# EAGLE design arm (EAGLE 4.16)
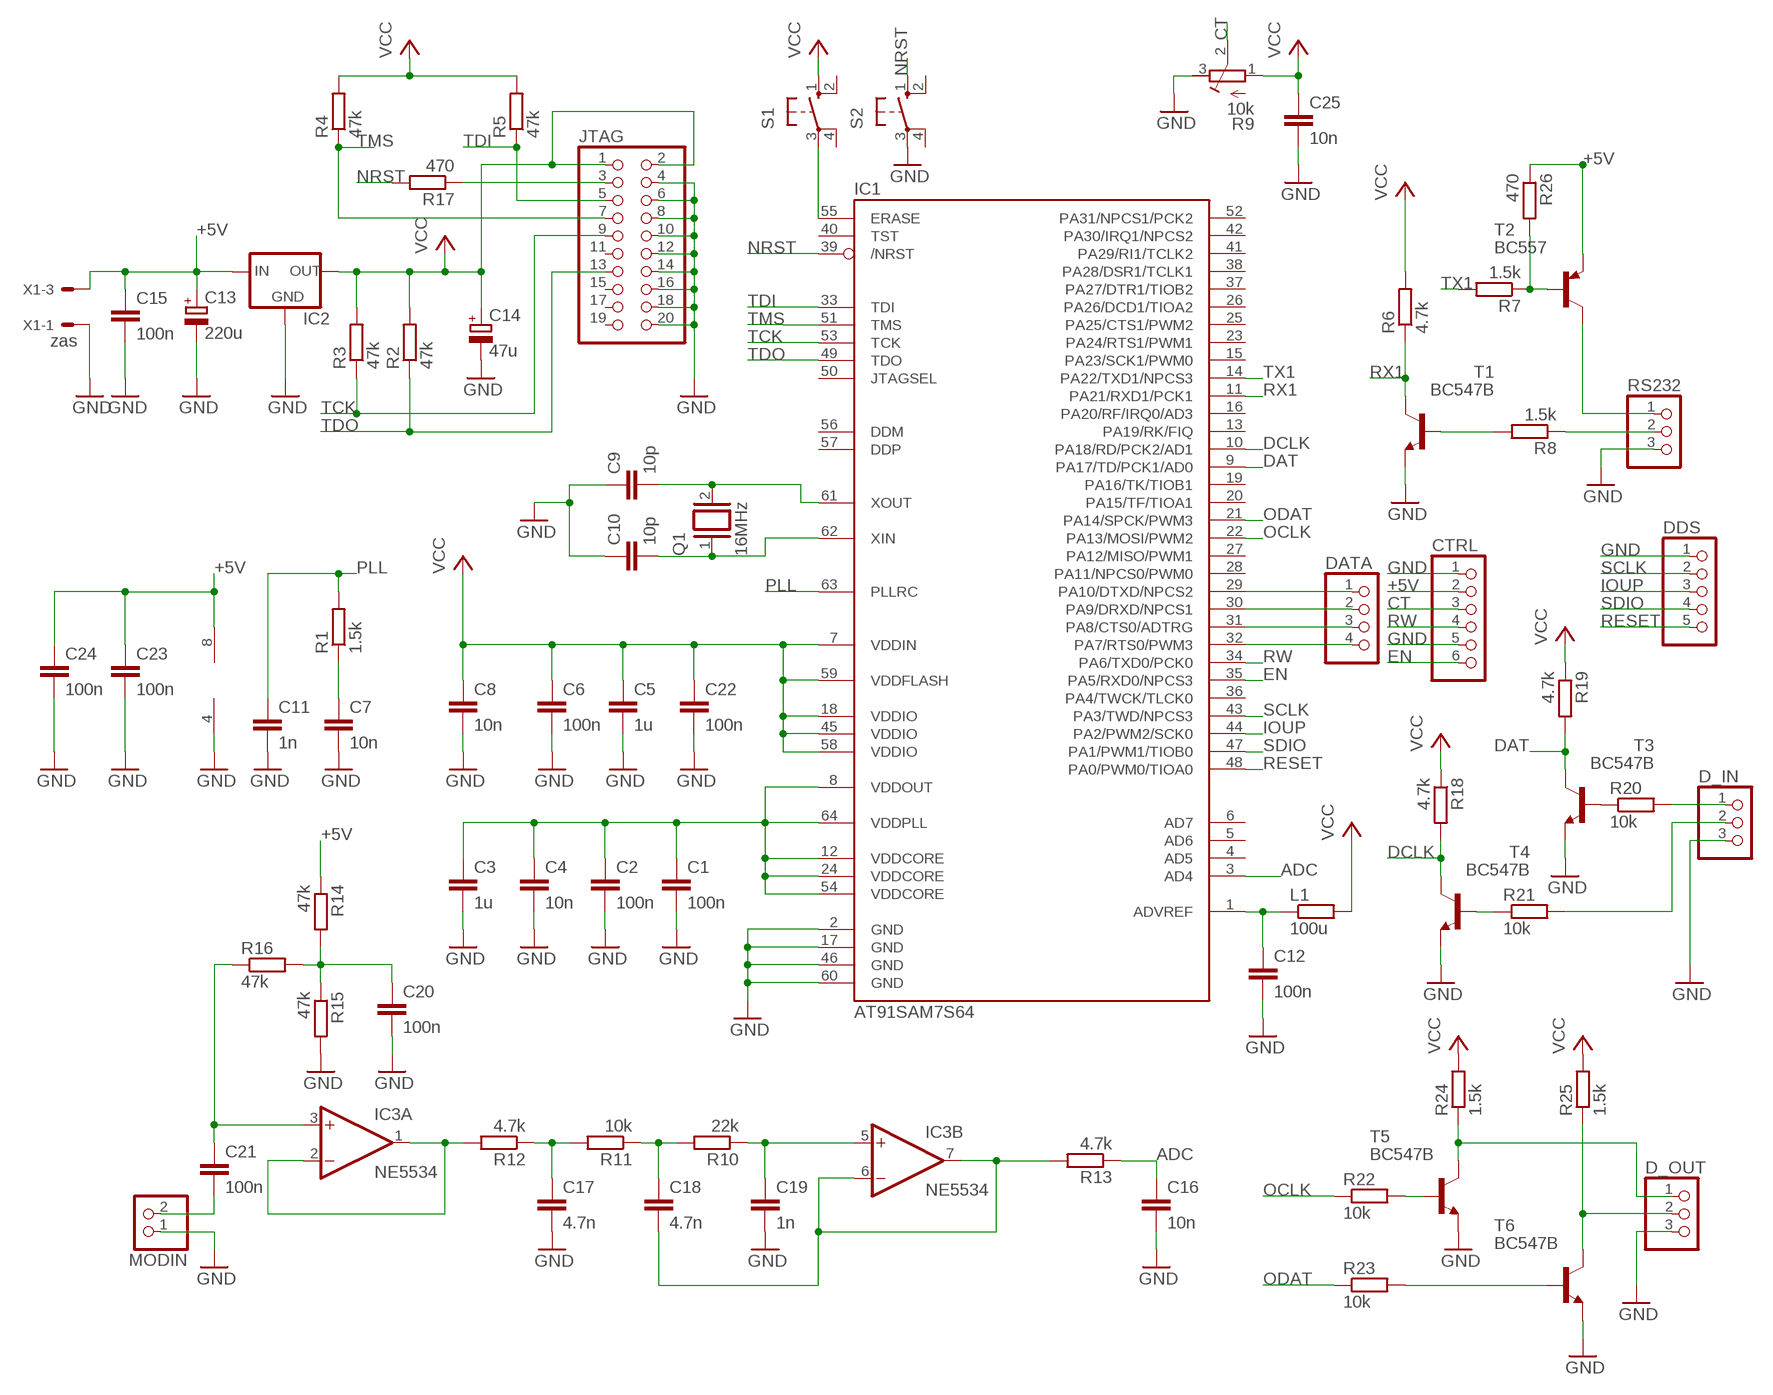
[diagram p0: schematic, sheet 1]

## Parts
C1  100n  C-EUC1206  [C1206]
C2  100n  C-EUC1206  [C1206]
C3  1u  C-EUC1210  [C1210]
C4  10n  C-EUC0805K  [C0805K]
C5  1u  C-EUC1210  [C1210]
C6  100n  C-EUC1206  [C1206]
C7  10n  C-EUC0805K  [C0805K]
C8  10n  C-EUC0805K  [C0805K]
C9  10p  C2.5/2  [C2.5-2]
C10  10p  C2.5/2  [C2.5-2]
C11  1n  C-EUC0603  [C0603]
C12  100n  C-EUC1206  [C1206]
C13  220u  CPOL-EUE2-5  [E2-5]
C14  47u  CPOL-EUE2-4  [E2-4]
C15  100n  C-EUC1206  [C1206]
C16  10n  C-EUC0805K  [C0805K]
C17  4.7n  C2.5/2  [C2.5-2]
C18  4.7n  C2.5/2  [C2.5-2]
C19  1n  C-EUC0603  [C0603]
C20  100n  C-EUC1206  [C1206]
C21  100n  C-EUC1206  [C1206]
C22  100n  C-EUC1206  [C1206]
C23  100n  C-EUC1206  [C1206]
C24  100n  C-EUC1206  [C1206]
C25  10n  C-EUC0805K  [C0805K]
CTRL  PINHD-1X6  [1X06]
D_IN  PINHD-1X3  [1X03]
D_OUT  PINHD-1X3  [1X03]
DATA  PINHD-1X4  [1X04]
DDS  PINHD-1X5  [1X05]
IC1  AT91SAM7S64  AT91SAM7S512/256/128/64/321-AU  [LQFP64]
IC2  78XXS  [78XXS]
IC3  NE5534  TL072P  [DIL08]
JTAG  PINHD-2X10  [2X10]
L1  100u  R-EU_0204/5  [0204/5]
MODIN  PINHD-1X2  [1X02]
Q1  16MHz  XTAL/S  [QS]
R1  1.5k  R-EU_R0603  [R0603]
R2  47k  R-EU_R0603  [R0603]
R3  47k  R-EU_R0603  [R0603]
R4  47k  R-EU_R0603  [R0603]
R5  47k  R-EU_R0603  [R0603]
R6  4.7k  R-EU_R0603  [R0603]
R7  1.5k  R-EU_R0603  [R0603]
R8  1.5k  R-EU_R0603  [R0603]
R9  10k  R-TRIMM3339P  [RTRIM3339P]
R10  22k  R-EU_R0603  [R0603]
R11  10k  R-EU_R0603  [R0603]
R12  4.7k  R-EU_R0603  [R0603]
R13  4.7k  R-EU_R0603  [R0603]
R14  47k  R-EU_R0603  [R0603]
R15  47k  R-EU_R0603  [R0603]
R16  47k  R-EU_R0603  [R0603]
R17  470  R-EU_R0603  [R0603]
R18  4.7k  R-EU_R0603  [R0603]
R19  4.7k  R-EU_R0603  [R0603]
R20  10k  R-EU_R0603  [R0603]
R21  10k  R-EU_R0603  [R0603]
R22  10k  R-EU_R0603  [R0603]
R23  10k  R-EU_R0603  [R0603]
R24  1.5k  R-EU_R0603  [R0603]
R25  1.5k  R-EU_R0603  [R0603]
R26  470  R-EU_R0603  [R0603]
RS232  PINHD-1X3  [1X03]
S1  10-XX  [B3F-10XX]
S2  10-XX  [B3F-10XX]
T1  BC547B  [TO92]
T2  BC557  [TO92]
T3  BC547B  [TO92]
T4  BC547B  [TO92]
T5  BC547B  [TO92]
T6  BC547B  [TO92]
X1  zas  22-23-2031  [22-23-2031]

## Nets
+5V: C13.+ C15.1 C23.1 C24.1 CTRL.2 IC2.IN IC3.8(P:V+) R14.1 R26.1 T2.1(E) X1.3
ADC: C16.1 IC1.3(AD4) R13.1
CT: CTRL.3 R9.2(S)
DAT: IC1.9(PA17/TD/PCK1/AD0) R19.2 T3.3(C)
DCLK: IC1.10(PA18/RD/PCK2/AD1) R18.2 T4.3(C)
EN: CTRL.6 IC1.35(PA5/RXD0/NPCS3)
GND: C1.2 C2.2 C3.2 C4.2 C5.2 C6.2 C7.2 C8.2 C9.1 C10.1 C11.2 C12.2 C13.- C14.- C15.2 C16.2 C17.2 C19.2 C20.2 C22.2 C23.2 C24.2 C25.2 CTRL.1 CTRL.5 D_IN.3 D_OUT.3 DDS.1 IC1.2(GND) IC1.17(GND) IC1.46(GND) IC1.60(GND) IC2.GND IC3.4(P:V-) JTAG.4 JTAG.6 JTAG.8 JTAG.10 JTAG.12 JTAG.14 JTAG.16 JTAG.18 JTAG.20 MODIN.1 R9.3(A) R15.2 RS232.3 S2.3(P) T1.1(E) T3.1(E) T4.1(E) T5.1(E) T6.1(E) X1.1
IOUP: DDS.3 IC1.44(PA2/PWM2/SCK0)
N$1: C1.1 C2.1 C3.1 C4.1 IC1.8(VDDOUT) IC1.12(VDDCORE) IC1.24(VDDCORE) IC1.54(VDDCORE) IC1.64(VDDPLL)
N$2: R7.1 R26.2 T2.2(B)
N$3: C10.2 IC1.62(XIN) Q1.1
N$4: C9.2 IC1.61(XOUT) Q1.2
N$5: C7.1 R1.1
N$6: R8.2 T1.2(B)
N$7: C21.2 MODIN.2
N$8: RS232.1 T2.3(C)
N$9: R8.1 RS232.2
N$10: C12.1 IC1.1(ADVREF) L1.1
N$11: DATA.1 IC1.29(PA10/DTXD/NPCS2)
N$12: DATA.2 IC1.30(PA9/DRXD/NPCS1)
N$13: DATA.3 IC1.31(PA8/CTS0/ADTRG)
N$14: DATA.4 IC1.32(PA7/RTS0/PWM3)
N$15: C18.2 IC3.6(B:-IN) IC3.7(B:OUT) R13.2
N$16: C17.1 R11.2 R12.1
N$17: IC1.55(ERASE) S1.3(P)
N$18: C18.1 R10.2 R11.1
N$19: C19.1 IC3.5(B:+IN) R10.1
N$20: JTAG.3 R17.1
N$21: R22.2 T5.2(B)
N$22: IC3.1(A:OUT) IC3.2(A:-IN) R12.2
N$23: R23.2 T6.2(B)
N$24: C21.1 IC3.3(A:+IN) R16.1
N$25: C20.1 R14.2 R15.1 R16.2
N$26: R21.1 T4.2(B)
N$27: R20.1 T3.2(B)
N$28: D_IN.1 R20.2
N$29: D_IN.2 R21.2
N$30: D_OUT.2 R25.1 T6.3(C)
N$31: D_OUT.1 R24.1 T5.3(C)
NRST: IC1.39(/NRST) R17.2 S2.1(S)
OCLK: IC1.22(PA13/MOSI/PWM2) R22.1
ODAT: IC1.21(PA14/SPCK/PWM3) R23.1
PLL: C11.1 IC1.63(PLLRC) R1.2
RESET: DDS.5 IC1.48(PA0/PWM0/TIOA0)
RW: CTRL.4 IC1.34(PA6/TXD0/PCK0)
RX1: IC1.11(PA21/RXD1/PCK1) R6.1 T1.3(C)
SCLK: DDS.2 IC1.43(PA3/TWD/NPCS3)
SDIO: DDS.4 IC1.47(PA1/PWM1/TIOB0)
TCK: IC1.53(TCK) JTAG.9 R3.1
TDI: IC1.33(TDI) JTAG.5 R5.1
TDO: IC1.49(TDO) JTAG.13 R2.1
TMS: IC1.51(TMS) JTAG.7 R4.1
TX1: IC1.14(PA22/TXD1/NPCS3) R7.2
VCC: C5.1 C6.1 C8.1 C14.+ C22.1 C25.1 IC1.7(VDDIN) IC1.18(VDDIO) IC1.45(VDDIO) IC1.58(VDDIO) IC1.59(VDDFLASH) IC2.OUT JTAG.1 JTAG.2 L1.2 R2.2 R3.2 R4.2 R5.2 R6.2 R9.1(E) R18.1 R19.1 R24.2 R25.2 S1.1(S)
Unconnected: IC1.4(AD5) IC1.5(AD6) IC1.6(AD7) IC1.13(PA19/RK/FIQ) IC1.15(PA23/SCK1/PWM0) IC1.16(PA20/RF/IRQ0/AD3) IC1.19(PA16/TK/TIOB1) IC1.20(PA15/TF/TIOA1) IC1.23(PA24/RTS1/PWM1) IC1.25(PA25/CTS1/PWM2) IC1.26(PA26/DCD1/TIOA2) IC1.27(PA12/MISO/PWM1) IC1.28(PA11/NPCS0/PWM0) IC1.36(PA4/TWCK/TLCK0) IC1.37(PA27/DTR1/TIOB2) IC1.38(PA28/DSR1/TCLK1) IC1.40(TST) IC1.41(PA29/RI1/TCLK2) IC1.42(PA30/IRQ1/NPCS2) IC1.50(JTAGSEL) IC1.52(PA31/NPCS1/PCK2) IC1.56(DDM) IC1.57(DDP) JTAG.11 JTAG.15 JTAG.17 JTAG.19 S1.2(S1) S1.4(P1) S2.2(S1) S2.4(P1) X1.2

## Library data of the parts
C1-C8 C11 C12 C15 C16 C19-C25 = rcl:C-EU: CAPACITOR, European symbol
C9 C10 C17 C18 = capacitor-wima:C: CAPACITOR
C13 C14 = rcl:CPOL-EU: POLARIZED CAPACITOR, European symbol
CTRL = pinhead:PINHD-1X6: PIN HEADER
D_IN D_OUT RS232 = pinhead:PINHD-1X3: PIN HEADER
DATA = pinhead:PINHD-1X4: PIN HEADER
DDS = pinhead:PINHD-1X5: PIN HEADER
IC1 = at91sam7sxxx-au:AT91SAM7S512/256/128/64/321
IC2 = v-reg:78XXS: VOLTAGE REGULATOR
IC3 = linear:TL072: OP AMP
JTAG = pinhead:PINHD-2X10: PIN HEADER
L1 R1-R8 R10-R26 = rcl:R-EU_: RESISTOR, European symbol
MODIN = pinhead:PINHD-1X2: PIN HEADER
Q1 = special:XTAL/S: CRYSTAL
R9 = rcl:R-TRIMM: Trimm resistor
S1 S2 = switch-omron:10-XX: OMRON SWITCH
T1 T3-T6 = transistor-npn:BC547*: NPN Transistor
T2 = transistor-pnp:BC557: PNP Transistor
X1 = con-molex:22-23-2031: .100" (2.54mm) Center Header - 3 Pin

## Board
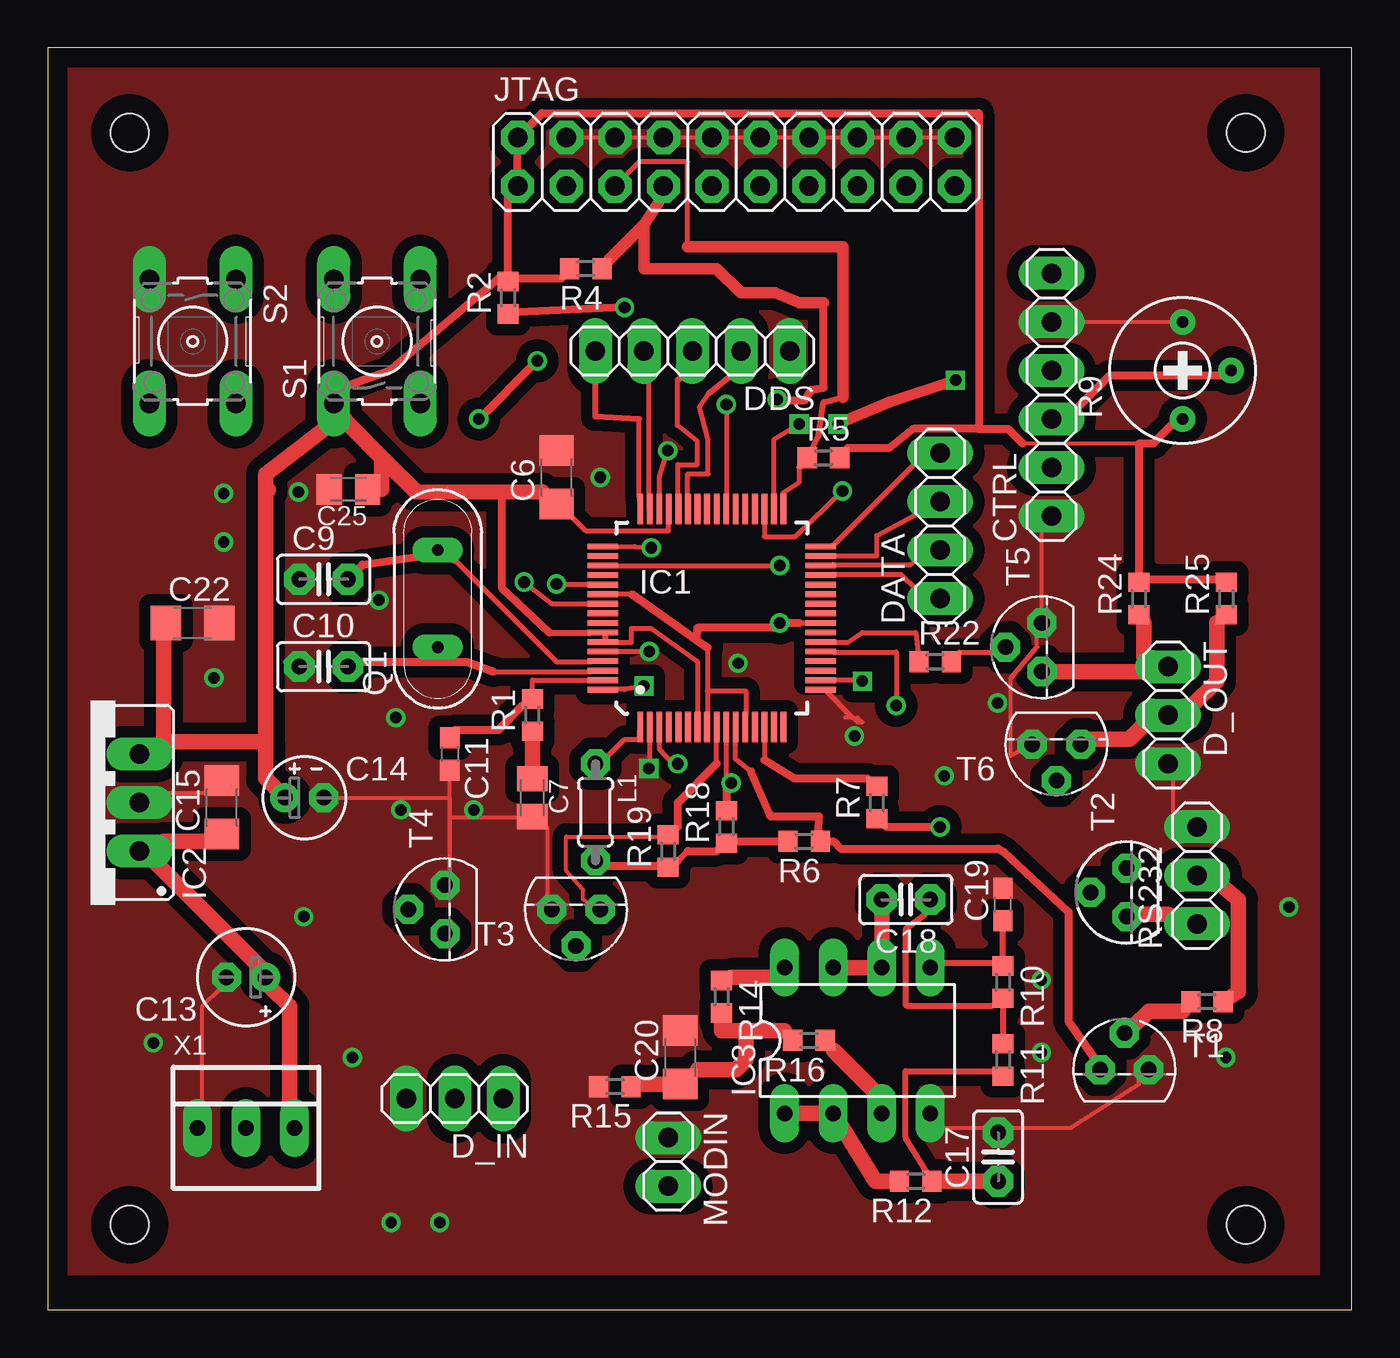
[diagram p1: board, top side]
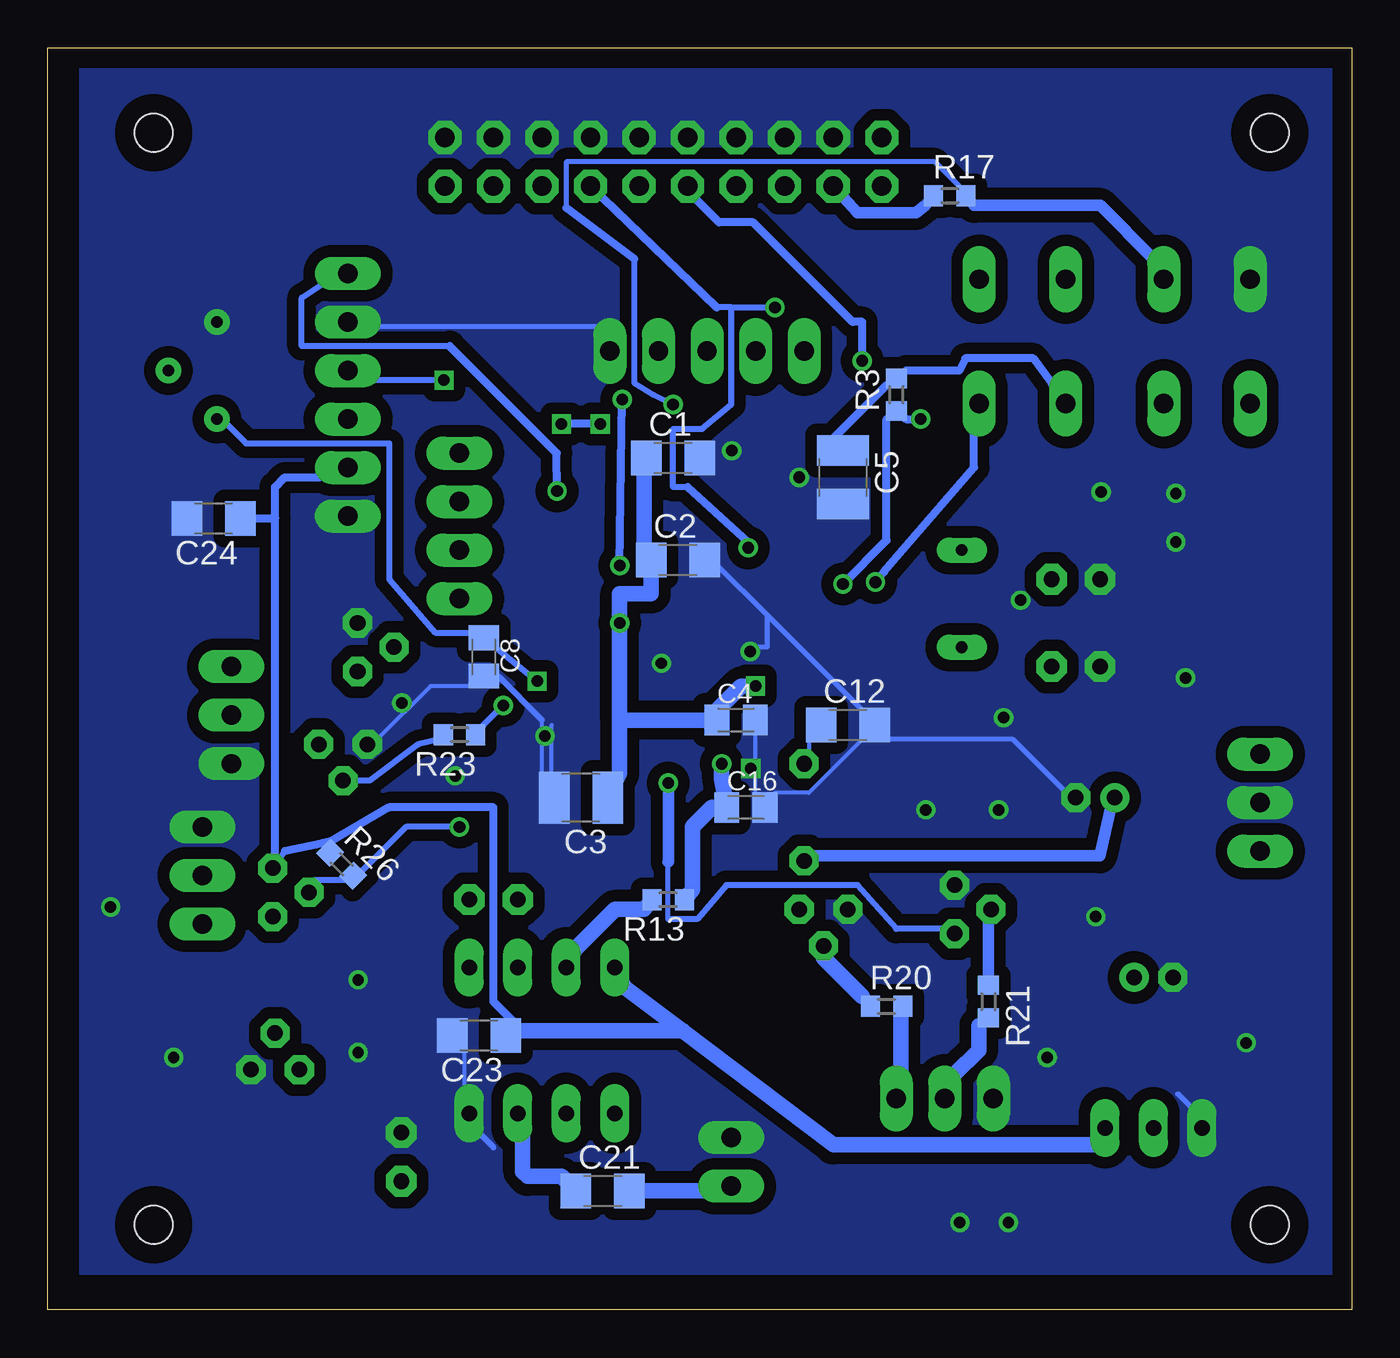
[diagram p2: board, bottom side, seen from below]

Size 68.25 x 66.03 mm. Coordinates in mm from the lower left corner, seen from the top.
Outline: 0,0 68.25,0 68.25,66.03 0,66.03 0,0
Copper layers (1*16): Top 0.035mm / dielectric 1.5mm / Bottom 0.035mm
Design rules "default": minimum track width 10mil, minimum drill 24mil, track to track 8mil, track to pad 8mil, pad to pad 8mil, via to via 8mil, smd to smd 8mil, copper to edge 40mil, drill to drill 8mil, minimum pad ring 14mil, minimum via ring 8mil, stop-mask expansion 4mil, vias tented up to drill 0mil, thermal gap 10mil
Holes 2 mm at 4.28,4.44 62.7,4.44 62.7,61.59 4.28,61.59

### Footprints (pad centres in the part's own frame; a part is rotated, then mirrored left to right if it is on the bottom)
C1206 = smd 1.6 x 1.8: 1 -1.4,0; 2 1.4,0
C1210 = smd 1.6 x 2.7: 1 -1.4,0; 2 1.4,0
C0805K = smd 1.3 x 1.6: 1 -1,0; 2 1,0
C2.5-2 = drill 0.813 pad 1.6 octagon: 1 -1.27,0; 2 1.27,0
C0603 = smd 1.1 x 1: 1 -0.85,0; 2 0.85,0
E2-5 = drill 0.813 pad 1.27 round: + -1.016,0 | drill 0.813 pad 1.27 octagon: - 1.016,0
E2-4 = drill 0.813 pad 1.27 round: + -1.016,0 | drill 0.813 pad 1.27 octagon: - 1.016,0
1X06 = drill 1.016 long: 1 -6.35,0; 2 -3.81,0; 3 -1.27,0; 4 1.27,0; 5 3.81,0; 6 6.35,0
1X03 = drill 1.016 long: 1 -2.54,0; 2 0,0; 3 2.54,0
1X04 = drill 1.016 long: 1 -3.81,0; 2 -1.27,0; 3 1.27,0; 4 3.81,0
1X05 = drill 1.016 long: 1 -5.08,0; 2 -2.54,0; 3 0,0; 4 2.54,0; 5 5.08,0
LQFP64 = smd 0.3 x 1.6: 1 -3.75,-5.7; 2 -3.25,-5.7; 3 -2.75,-5.7; 4 -2.25,-5.7; 5 -1.75,-5.7; 6 -1.25,-5.7; 7 -0.75,-5.7; 8 -0.25,-5.7; 9 0.25,-5.7; 10 0.75,-5.7; 11 1.25,-5.7; 12 1.75,-5.7; 13 2.25,-5.7; 14 2.75,-5.7; 15 3.25,-5.7; 16 3.75,-5.7; 33 3.75,5.7; 34 3.25,5.7; 35 2.75,5.7; 36 2.25,5.7; 37 1.75,5.7; 38 1.25,5.7; 39 0.75,5.7; 40 0.25,5.7; 41 -0.25,5.7; 42 -0.75,5.7; 43 -1.25,5.7; 44 -1.75,5.7; 45 -2.25,5.7; 46 -2.75,5.7; 47 -3.25,5.7; 48 -3.75,5.7 | smd 1.6 x 0.3: 17 5.7,-3.75; 18 5.7,-3.25; 19 5.7,-2.75; 20 5.7,-2.25; 21 5.7,-1.75; 22 5.7,-1.25; 23 5.7,-0.75; 24 5.7,-0.25; 25 5.7,0.25; 26 5.7,0.75; 27 5.7,1.25; 28 5.7,1.75; 29 5.7,2.25; 30 5.7,2.75; 31 5.7,3.25; 32 5.7,3.75; 49 -5.7,3.75; 50 -5.7,3.25; 51 -5.7,2.75; 52 -5.7,2.25; 53 -5.7,1.75; 54 -5.7,1.25; 55 -5.7,0.75; 56 -5.7,0.25; 57 -5.7,-0.25; 58 -5.7,-0.75; 59 -5.7,-1.25; 60 -5.7,-1.75; 61 -5.7,-2.25; 62 -5.7,-2.75; 63 -5.7,-3.25; 64 -5.7,-3.75
78XXS = drill 1.016 long: GND 0,-2.54; IN -2.54,-2.54; OUT 2.54,-2.54
DIL08 = drill 0.813 long: 1 -3.81,-3.81; 2 -1.27,-3.81; 3 1.27,-3.81; 4 3.81,-3.81; 5 3.81,3.81; 6 1.27,3.81; 7 -1.27,3.81; 8 -3.81,3.81
2X10 = drill 1.016 octagon: 1 -11.43,-1.27; 2 -11.43,1.27; 3 -8.89,-1.27; 4 -8.89,1.27; 5 -6.35,-1.27; 6 -6.35,1.27; 7 -3.81,-1.27; 8 -3.81,1.27; 9 -1.27,-1.27; 10 -1.27,1.27; 11 1.27,-1.27; 12 1.27,1.27; 13 3.81,-1.27; 14 3.81,1.27; 15 6.35,-1.27; 16 6.35,1.27; 17 8.89,-1.27; 18 8.89,1.27; 19 11.43,-1.27; 20 11.43,1.27
0204/5 = drill 0.813 octagon: 1 -2.54,0; 2 2.54,0
1X02 = drill 1.016 long: 1 -1.27,0; 2 1.27,0
QS = drill 0.61 long: 1 -2.54,0; 2 2.54,0
R0603 = smd 1 x 1.1: 1 -0.85,0; 2 0.85,0
RTRIM3339P = drill 0.61 round: 1 -2.54,0; 2 0,-2.54; 3 2.54,0
B3F-10XX = drill 1.016 long: 1 -3.251,2.261; 2 3.251,2.261; 3 -3.251,-2.261; 4 3.251,-2.261
TO92 = drill 0.813 octagon: 1 1.27,0; 2 0,1.905; 3 -1.27,0
22-23-2031 = drill 0.813 long: 1 -2.54,0; 2 0,0; 3 2.54,0

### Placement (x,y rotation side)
C1  35.52,44.57 0 bottom
C2  35.27,39.24 0 bottom
C3  40.35,26.79 180 bottom
C4  32.22,30.86 0 bottom
C5  26.63,43.56 270 bottom
C6  26.63,43.56 90 top
C7  25.36,26.79 270 top
C8  45.43,34.16 270 bottom
C9  14.44,38.22 0 top
C10  14.44,33.65 0 top
C11  21.04,29.08 270 top
C12  26.38,30.6 0 bottom
C13  10.38,17.39 180 top
C14  13.42,26.79 0 top
C15  9.11,26.28 90 top
C16  31.71,26.28 0 bottom
C17  49.75,8 90 top
C18  44.92,21.46 180 top
C19  50,21.2 90 top
C20  33.11,13.2 90 top
C21  39.2,6.22 0 bottom
C22  7.58,35.94 0 top
C23  45.68,14.35 180 bottom
C24  59.58,41.4 180 bottom
C25  15.74,42.92 180 top
CTRL  52.54,47.87 90 top
D_IN  21.3,11.04 180 top
D_OUT  58.64,31.11 270 top
DATA  46.7,41.02 90 top
DDS  33.74,50.16 180 top
IC1  34.76,36.19 0 top
IC2  2.25,26.54 90 top
IC3  42.38,14.09 0 top
JTAG  36.03,60.07 0 top
L1  28.66,26.03 270 top
MODIN  32.47,7.74 270 top
Q1  20.41,37.21 90 top
R1  25.36,31.11 90 top
R2  24.09,52.95 90 top
R3  23.84,47.87 90 bottom
R4  28.16,54.48 180 top
R5  40.6,44.57 0 top
R6  39.59,24.51 180 top
R7  43.4,26.54 90 top
R8  60.67,16.12 180 top
R9  59.4,49.14 90 top
R10  50,17.14 270 top
R11  50,13.08 270 top
R12  45.43,6.73 180 top
R13  35.78,21.46 180 bottom
R14  35.27,16.38 270 top
R15  29.68,11.68 180 top
R16  39.84,14.09 180 top
R17  21.04,58.29 0 bottom
R18  35.52,25.27 90 top
R19  32.47,24 90 top
R20  24.35,15.87 0 bottom
R21  19.01,16.12 270 bottom
R22  46.44,33.9 0 top
R23  46.7,30.09 180 bottom
R24  57.11,37.21 90 top
R25  61.68,37.21 90 top
R26  52.87,23.31 315 bottom
RS232  60.16,22.73 90 top
S1  17.23,50.67 90 top
S2  7.58,50.67 270 top
T1  56.35,12.57 0 top
T2  56.48,21.84 90 top
T3  27.65,20.95 180 top
T4  20.79,20.95 90 top
T5  52.03,34.67 90 top
T6  52.79,29.59 180 top
X1  10.38,9.52 0 top

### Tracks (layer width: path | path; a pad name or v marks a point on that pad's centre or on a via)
+5V
  Top 0.203: 8.34,24.51 C15.1 | C13.+ 11.14,17.9 | 35.78,17.39 R14.1
  Top 0.813: 8.34,24.51 6.06,24.51 IC2.IN 5.55,23.49 11.14,17.9 | X1.3 12.66,10.79 12.66,15.87 11.65,16.89 C13.+ | 35.78,17.39 38.06,17.39 IC3.8
  Bottom 0.203: 43.65,14.6 C23.1 43.9,15.11 | 35.02,14.59 35.01,14.6
  Bottom 0.254: R26.1 53.81,24.25 53.84,24.42
  Bottom 0.305: 55.84,24 T2.1
  Bottom 0.406: 55.84,24 53.84,24.42 53.43,24.51 50.38,26.28 44.92,26.28 44.92,16.12 43.9,15.11 | 56.35,41.45 56.35,23.74 T2.1 | 56.35,41.45 56.35,43.05 55.84,43.56 54.06,43.56 CTRL.2 | C24.1 56.35,41.4 56.35,41.45
  Bottom 0.813: X1.3 13.42,8.63 27.14,8.63 35.02,14.59 38.06,16.89 IC3.8 | 35.01,14.6 43.65,14.6
ADC  (via drill 0.61)
  Top 0.203: v32.98,28.57 32.73,28.57 | 32.02,29.84 IC1.3
  Top 0.254: 32.02,29.84 32.02,29.33 32.73,28.57
  Bottom 0.813: R13.1 34.51,21.97 34.51,25.27 33.49,26.28 C16.1 32.98,27.81 v32.98,28.57
CT
  Top 0.406: R9.2 61.43,48.89 55.59,48.89 53.81,47.11 CTRL.3
DAT
  Top 0.203: 32.98,25.27 R19.2 31.97,24.76 27.14,24.76 27.14,22.98 28.03,21.97 28.03,21.46 T3.3 | 35.01,29.84 IC1.9
  Top 0.254: 35.01,28.57 35.01,29.84
  Top 0.406: 32.98,25.27 32.98,26.54 35.01,28.57
DCLK  (via drill 0.61)
  Top 0.203: 35.52,29.84 IC1.10 | v35.78,27.55 35.52,27.55
  Top 0.254: 35.52,27.55 35.52,29.84
  Top 0.406: 35.52,27.55 R18.2
  Bottom 0.254: 35.78,20.44 35.78,23.44
  Bottom 0.305: 35.78,20.44 34.25,20.44 32.73,22.22 25.87,22.22 23.84,19.93 21.3,19.93 T4.3
  Bottom 0.61: v35.78,27.55 35.75,27.55 35.75,23.44 35.78,23.44
EN  (via drill 0.61)
  Top 0.254: v41.59,42.84 39.1,40.46 37.5,40.46 37.5,41.27 IC1.35
  Bottom 0.305: 51.27,54.48 CTRL.6 53.81,53.72 54.95,52.95 54.95,50.41 47.21,50.41
  Bottom 0.406: v41.59,42.84 41.62,44.83 47.21,50.41
GND  (via drill 0.6, 0.61)
  Top 0.203: X1.1 8.09,10.79 8.09,15.87 9.11,16.89 C13.- | 21.04,25.78 21.04,22.73 T4.1 | 21.04,26.79 21.04,25.78 | 21.04,26.79 C11.2 | 21.04,25.78 24.6,25.78 C7.2 26.12,25.27 26.12,21.46 T3.1 | 21.04,26.79 C14.- 13.93,27.05 | C15.2 8.34,27.05 6.06,27.05 IC2.GND | 12.41,33.9 C10.1 | 9.61,36.7 C22.2 9.11,35.17 | JTAG.20 JTAG.18 JTAG.16 JTAG.14 JTAG.12 JTAG.10 JTAG.8 JTAG.6 JTAG.4 | CTRL.1 52.03,41.02 T5.1 51.78,35.43 51.78,34.67 | T1.1 57.11,12.31 57.11,11.81 53.56,9.52 50.51,9.52 C17.2 48.98,9.52 46.7,9.52 IC3.4 | D_OUT.3 58.89,28.06 58.89,25.78 RS232.3 | 50.41,33.04 50.41,28.98 T6.1 | v31.46,28.32 31.51,28.37 | CTRL.5 R9.3 | IC1.17 40.67,32.44 | 42.13,30.98 42.38,30.73 42.63,30.73 42.38,30.98 42.13,30.98 | 42.13,30.98 41.75,30.98
  Top 0.254: 50.41,33.04 51.78,34.67 | 31.51,28.37 IC1.2 | 40.67,32.44 42.13,30.98 | IC1.60 31.15,34.44 v31.48,34.44 | IC1.46 32.02,43.58 v32.45,44.95
  Bottom 0.203: D_IN.3 18.25,11.3 | C23.2 46.44,13.58 46.44,11.55 IC3.4 45.68,9.27 | MODIN.1 33.74,8.5 | 51.27,51.43 CTRL.5 | JTAG.16 42.89,60.83 | C12.2 25.62,29.84 28.41,27.05 30.19,27.05 C16.2 31.2,27.05 31.2,28.32 | 24.35,29.84 C12.2 | C14.- 14.95,27.05 | C12.2 25.62,31.36 | 31.2,28.32 31.2,30.09 C4.2 | T6.1 51.02,29.84 48.22,32.63 46.19,32.63 C8.2 44.67,33.14 | 42.38,30.86 42.38,28.06 C3.2 | 31.2,28.32 v31.46,28.32 | 41.87,27.81 41.87,30.6
  Bottom 0.254: 9.11,11.3 8.34,10.54 X1.1 | 51.27,51.43 39.33,51.43 DDS.1 | 24.35,29.84 17.74,29.84 14.95,27.05 | 25.62,31.36 30.56,36.3 | 30.56,36.3 33.24,38.98 C2.2 | v31.48,34.44 31.33,34.46 31.33,34.67 30.59,34.67 30.59,36.3 30.56,36.3 | v32.45,44.95 32.55,45.28
  Bottom 0.305: 45.68,9.27 44.92,8.5 | 42.38,30.86 44.67,33.14
  Bottom 0.406: 26.66,42.29 26.66,42.16 C5.2
  other vias: 28.92,43.56 13.12,42.79 9.21,42.72 9.21,40.18 8.7,33.07 17.34,37.13 42.23,30.02 36.13,33.83 22.29,26.16 18.48,26.16 18.22,30.98 17.97,4.57 20.51,4.57 49.72,31.74 13.4,20.57 15.94,13.2 5.52,13.96 52.01,17.27 52.01,13.46 61.66,13.2 64.96,21.08 46.93,27.93
  pour Top (isolate 0.61, no thermals): 0.47,65.4 0.47,1.9 66.51,1.9 66.51,65.4
  pour Bottom (isolate 0.61, no thermals): 0.47,65.4 0.47,1.9 66.51,1.9 66.51,65.4
IOUP
  Top 0.203: IC1.44 32.98,42.54
  Top 0.254: 32.98,42.54 32.98,44.22 34,44.22 34,45.44 32.96,46.27 32.96,48.69 32.98,48.64
  Top 0.305: 32.98,48.64 33.24,48.89 DDS.3
N$1  (via drill 0.6, 0.61)
  Top 0.203: 36.49,31.13 IC1.12 | 39.84,35.94 IC1.24 | 29.68,37.43 IC1.54 | 34.53,31.11 IC1.8
  Top 0.254: 39.33,35.94 39.84,35.94 | 30.57,37.43 29.68,37.43 | 34.53,32.38 34.53,31.11 | 34.53,34.64 34.53,32.38 | v31.2,32.63 30.19,32.46 29.17,32.46 IC1.64 | 36.49,31.13 36.54,31.13 36.54,32.38 34.53,32.38 | 34.53,32.38 34.51,32.38 | v38.32,35.94 38.06,35.68
  Top 0.406: v38.32,35.94 39.33,35.94 | 33.92,35.07 34.53,34.64 | 33.92,35.07 30.57,37.43 | 38.06,35.68 34,35.68 33.92,35.07
  Bottom 0.254: 37.05,43.81 C1.1 | C2.1 37.05,40
  Bottom 0.813: 38.32,30.86 v38.32,35.94 38.32,37.46 36.67,37.46 C2.1 | 38.32,30.86 38.32,28.06 C3.1 | 38.32,30.86 C4.1 33.22,31.38 31.97,32.63 v31.2,32.63 | 37.05,40 37.05,43.81
N$2  (via drill 0.61)
  Top 0.406: v46.7,25.27 43.9,25.27 R7.1
  Bottom 0.254: 52.03,22.73 R26.2
  Bottom 0.305: v46.7,25.27 49.49,25.27 52.03,22.73 52.29,22.47 54.32,22.47 T2.2
N$3
  Top 0.203: 28.41,33.4 IC1.62
  Top 0.254: 23.33,33.4 28.41,33.4 | 20.54,33.9 20.54,34.16
  Top 0.406: 23.33,33.4 21.93,33.9 20.54,33.9 16.47,33.9 C10.2 | 20.54,34.16 Q1.1
N$4
  Top 0.203: 28.41,33.9 IC1.61
  Top 0.254: 28.41,33.9 26.63,33.9 21.3,39.24
  Top 0.406: 21.3,39.24 Q1.2 20.03,39.49 16.47,38.98 C9.2
N$5
  Top 0.813: C7.1 R1.1
N$6
  Top 0.203: 59.4,15.62 R8.2
  Top 0.813: 59.4,15.62 57.62,15.62 56.86,14.85 T1.2
N$7
  Bottom 0.813: C21.2 34,6.22 MODIN.2
N$8
  Top 0.813: T2.3 57.11,20.7 58.64,20.7 RS232.1
N$9
  Top 0.813: R8.1 62.32,16.63 62.32,21.46 61.43,22.22 RS232.2
N$10
  Top 0.254: IC1.1 30.95,29.84 30.19,29.84 29.17,28.82 L1.1
  Bottom 0.203: C12.1 28.41,29.84 28.41,29.08 L1.1
N$11
  Top 0.203: IC1.29 41.11,38.48
  Top 0.254: 41.11,38.48 44.67,38.48 45.43,37.71 DATA.1
N$12
  Top 0.203: 45.17,38.98 45.43,39.24 | IC1.30 41.11,38.98
  Top 0.254: 41.11,38.98 45.17,38.98 | 45.43,39.24 DATA.2
N$13
  Top 0.254: IC1.31 43.4,39.44 43.4,40.51 DATA.3
N$14
  Top 0.203: IC1.32 41.11,40
  Top 0.254: 41.11,40 45.43,44.32 DATA.4
N$15
  Top 0.813: IC3.7 IC3.6 C18.2
  Bottom 0.813: R13.2 37.05,20.95 38.57,20.95 40.6,18.92 IC3.7
N$16
  Top 0.305: 46.29,6.73 44.89,9.01 44.89,12.49 49.57,12.49 R11.2
  Top 0.406: R12.1 46.29,6.73
  Top 0.813: 46.29,6.73 C17.1
N$17  (via drill 0.61)
  Top 0.254: v24.93,38.07 26.38,36.95 28.41,36.95 IC1.55
  Bottom 0.406: v24.93,38.07 24.47,38.6 19.77,44.06 19.77,46.1 S1.3
N$18
  Top 0.203: 49.47,15.92 R10.2
  Top 0.305: R10.2 R11.1 | 49.47,15.92 44.92,15.92 44.92,19.93 45.94,20.7 C18.1
N$19
  Top 0.203: 49.49,18.16 R10.1
  Top 0.305: R10.1 C19.1 | 49.49,18.16 46.7,18.16 IC3.5
N$20
  Bottom 0.61: R17.1 22.31,57.78 22.82,57.4 25.87,57.4 JTAG.3
N$21
  Top 0.254: R22.2 47.71,34.41 49.49,34.41 T5.2
N$22
  Top 0.813: R12.2 43.32,6.73 IC3.2 IC3.1
N$23
  Bottom 0.305: R23.2 47.71,29.84 48.86,29.59 51.4,27.68 T6.2
N$24
  Top 0.305: 41.11,13.58 R16.1
  Top 0.813: 41.11,13.58 43.4,11.3 IC3.3
  Bottom 0.813: C21.1 41.36,6.98 43.14,6.98 43.4,7.23 43.4,9.01 IC3.3
N$25
  Top 0.203: 38.57,14.6 R16.2 | R15.1 30.95,11.81 | 32.22,11.81 C20.1 34,12.57
  Top 0.813: 36.54,14.6 35.27,14.6 R14.2 | 36.54,14.6 38.57,14.6 | 30.95,11.81 32.22,11.81 | 34,12.57 36.03,12.57 36.54,13.08 36.54,14.6
N$26
  Bottom 0.61: R21.1 19.01,20.44 T4.2
N$27
  Bottom 0.305: R20.1 25.62,16.38
  Bottom 0.813: 25.62,16.38 27.65,18.41 T3.2
N$28
  Bottom 0.203: 23.58,15.36 R20.2
  Bottom 0.813: 23.58,15.36 23.58,12.31 D_IN.1
N$29
  Bottom 0.305: 19.52,14.85 R21.2
  Bottom 0.813: 19.52,14.85 19.52,13.58 20.79,12.31 D_IN.2
N$30
  Top 0.203: 61.18,35.94 R25.1
  Top 0.813: 61.18,35.94 61.18,32.89 59.91,31.62 D_OUT.2 57.37,30.6 56.6,29.84 54.57,29.84 T6.3
N$31
  Top 0.203: 57.37,35.94 R24.1 | 57.37,33.4 D_OUT.1
  Top 0.813: 57.37,35.94 57.37,34.16 D_OUT.1 | T5.3 57.37,33.4
NRST  (via drill 0.61)
  Top 0.203: 35.52,42.54 IC1.39
  Top 0.254: v35.52,47.37 35.52,42.54
  Bottom 0.254: 19.77,57.78 R17.2 20.54,58.8 21.81,60.07 41.11,60.07 41.11,57.65
  Bottom 0.305: v35.52,47.37 36.54,47.87 37.55,48.51 37.55,54.99
  Bottom 0.406: 41.11,57.65 37.55,54.99
  Bottom 0.61: 19.77,57.78 13.17,57.78 10.38,54.99 S2.1
OCLK
  Top 0.254: R22.1 45.43,35.43 42.63,35.43 41.87,34.92 41.11,34.92 IC1.22
ODAT  (via drill 0.61)
  Top 0.203: IC1.21 41.11,34.41
  Top 0.254: v44.41,31.62 44.41,34.41 41.11,34.41
  Bottom 0.305: v44.41,31.62 45.43,30.6 R23.1
PLL
  Top 0.254: IC1.63 25.36,32.94 R1.2
  Top 0.406: C11.1 21.3,30.35 23.58,30.35 24.85,31.62 R1.2 25.36,31.87
RESET
  Top 0.203: IC1.48 30.95,42.54
  Top 0.254: 30.95,42.54 30.95,46.6
  Top 0.305: DDS.5 28.66,46.73 30.95,46.6
RW  (via drill 0.6)
  Top 0.254: IC1.34 38.01,45.54 v39.33,46.35
  Top 0.61: v41.36,46.35 44.03,47.49 v47.51,48.64
  Bottom 0.305: v47.51,48.64 52.03,48.64 CTRL.4
  Bottom 0.406: v39.33,46.35 v41.36,46.35
RX1
  Top 0.203: 36,29.81 IC1.11 | 55.21,12.57 T1.3
  Top 0.254: 36,29.81 36,28.8 36.82,28.16
  Top 0.406: 55.21,12.57 53.43,15.11 53.43,20.82 50.07,23.94 49.75,24.12 41.49,24.12 41.11,24.51 R6.1 40.35,25.01 40.37,25.8 37.83,25.8 37.81,25.9 36.82,28.16
SCLK
  Top 0.203: IC1.43 33.49,42.54
  Top 0.254: 33.49,42.54 33.49,43.73 34.56,43.73 34.56,45.54 34.1,47.24 34.61,47.95
  Top 0.305: 34.61,47.95 35.78,48.89 DDS.2
SDIO
  Top 0.203: IC1.47 31.46,41.89
  Top 0.254: 31.46,41.89 31.46,49.91
  Top 0.305: 31.46,49.91 DDS.4
TCK  (via drill 0.61)
  Top 0.203: 28.41,37.97 IC1.53
  Top 0.254: v26.63,37.97 28.41,37.97
  Top 0.406: v22.57,46.6 v25.62,49.65
  Bottom 0.406: v26.63,37.97 24.35,40.25 24.35,46.6 R3.1 23.33,46.6 v22.57,46.6 | v25.62,49.65 25.62,51.68 26.12,51.68 31.33,56.89 33.11,56.89 34.89,58.67 JTAG.9
TDI
  Top 0.254: 39.33,44.06 39.33,43.3 38.49,42.74 IC1.33 | JTAG.5 30.95,60.07 33.49,60.07 33.49,55.62
  Top 0.305: 39.33,44.06 R5.1 40.35,45.71 40.6,47.49 41.62,47.75
  Top 0.61: 41.62,47.75 41.62,55.62 33.49,55.62
TDO  (via drill 0.61)
  Top 0.254: v31.59,39.87 30.72,39.92 IC1.49
  Top 0.305: 24.6,52.19 R2.1
  Top 0.406: v30.19,52.45 24.6,52.19
  Bottom 0.203: v31.59,39.87 31.59,40.13
  Bottom 0.305: 32.47,52.45 33.24,52.45 | 32.47,52.45 v30.19,52.45 | 34.76,43.05 35.52,43.05 35.52,46.1 34,46.1 32.47,47.37 32.47,52.45
  Bottom 0.406: 33.24,52.45 JTAG.13 | 31.59,40.13 34.76,43.05
TMS  (via drill 0.61)
  Top 0.203: IC1.51 29.68,38.93 | v38.19,47.62 38.49,47.59
  Top 0.254: 29.68,38.93 v38.32,38.93
  Top 0.406: 40.6,52.7 40.6,48.25 39.97,48.13 39.64,47.59 38.49,47.59
  Top 0.61: 31.2,56.76 29.43,54.99 R4.1 | 31.2,56.76 32.22,58.34 JTAG.7 | 31.2,56.76 31.2,54.48 35.01,54.48 36.28,53.21 38.06,53.21 39.33,52.7 40.6,52.7
  Bottom 0.406: v38.32,38.93 v38.19,47.62
TX1
  Top 0.203: 37.5,29.74 IC1.14
  Top 0.254: 37.5,29.74 37.5,28.77
  Top 0.406: 37.5,28.77 39.08,27.81 42.89,27.81 R7.2
VCC  (via drill 0.6)
  Top 0.203: 31.97,23.24 R19.1 | 35.01,24 R18.1 36.03,24.51 | 6.06,35.17 C22.1 | R24.2 57.62,38.22 | 61.18,38.22 R25.2 | 29.17,35.02 IC1.59 | IC1.58 29.17,35.43 | 32.5,41.27 IC1.45 | C6.1 27.39,41.52 | 26.89,53.97 R4.2 | 34,31.11 IC1.7 | v42.63,32.89 42.63,32.94 | 51.02,45.33 57.11,45.33 | 6.06,29.59 6.19,29.71
  Top 0.254: 32.5,41.27 32.5,40.76 28.16,40.76 27.39,41.52 | 25.87,42.79 C6.1 | 34,31.11 34,33.93 33.95,33.95 31.59,35.66 30.54,35.66 30.54,34.92 29.68,34.92 IC1.59 | 42.63,32.94 IC1.18
  Top 0.305: 32.98,23.49 33.49,24 | 29.17,35.43 29.17,35.02 | 24.6,53.97 R2.2 23.58,53.97 | 26.25,35.43 28.41,35.43 IC1.58 | 41.87,45.08 R5.2
  Top 0.406: 31.97,23.24 29.17,23.24 L1.2 | 33.49,24 35.01,24 | R19.1 32.98,23.49 | 57.62,38.22 61.18,38.22 | 24.6,53.97 26.89,53.97 | R2.2 24.09,58.29 JTAG.1 JTAG.2 25.87,62.61 48.73,62.61 48.73,46.1 | 23.58,53.97 17.87,49.14 15.71,48.38 S1.1 | 26.25,35.43 23.76,37.79 23.76,42.77 | 41.87,45.08 44.03,45.08 45.3,46.1 48.73,46.1 | 48.73,46.1 50.25,46.1 51.02,45.33 | R9.1 58.89,46.35 57.87,45.33 57.11,45.33 R24.2 | 36.03,24.51 R6.2
  Top 0.813: 6.06,35.17 6.06,29.59 IC2.OUT | 25.87,42.79 23.76,42.77 19.27,42.79 17.69,44.37 | 15.71,46.35 17.69,44.37 | 15.71,46.35 S1.1 | C14.+ 11.39,27.81 11.39,29.71 | 11.39,29.71 11.39,42.92 | 11.39,42.92 11.39,43.71 14.82,46.35 15.71,46.35 | 6.19,29.71 11.39,29.71 | 11.39,42.92 11.54,42.92 11.54,42.87 | 17.69,44.37 17.46,44.37 17.46,42.92 C25.1
  Bottom 0.203: R3.2 24.35,48.38 | 27.14,45.59 C5.1 | 45.43,35.17 C8.1 46.19,35.43
  Bottom 0.305: C14.+ 12.56,26.54 | 23.33,49.14 R3.2 | 45.43,35.17 v42.63,32.89 | 46.19,35.43 47.97,35.43 50.38,38.22 50.38,45.33 57.87,45.33 58.89,46.35 R9.1
  Bottom 0.406: 24.35,48.38 27.14,45.59 | 23.33,49.14 20.54,49.14 20.23,49.78 16.68,49.78 15.71,48.51 S1.1
  Bottom 0.61: 12.56,26.54 13.2,23.74 28.16,23.74 L1.2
